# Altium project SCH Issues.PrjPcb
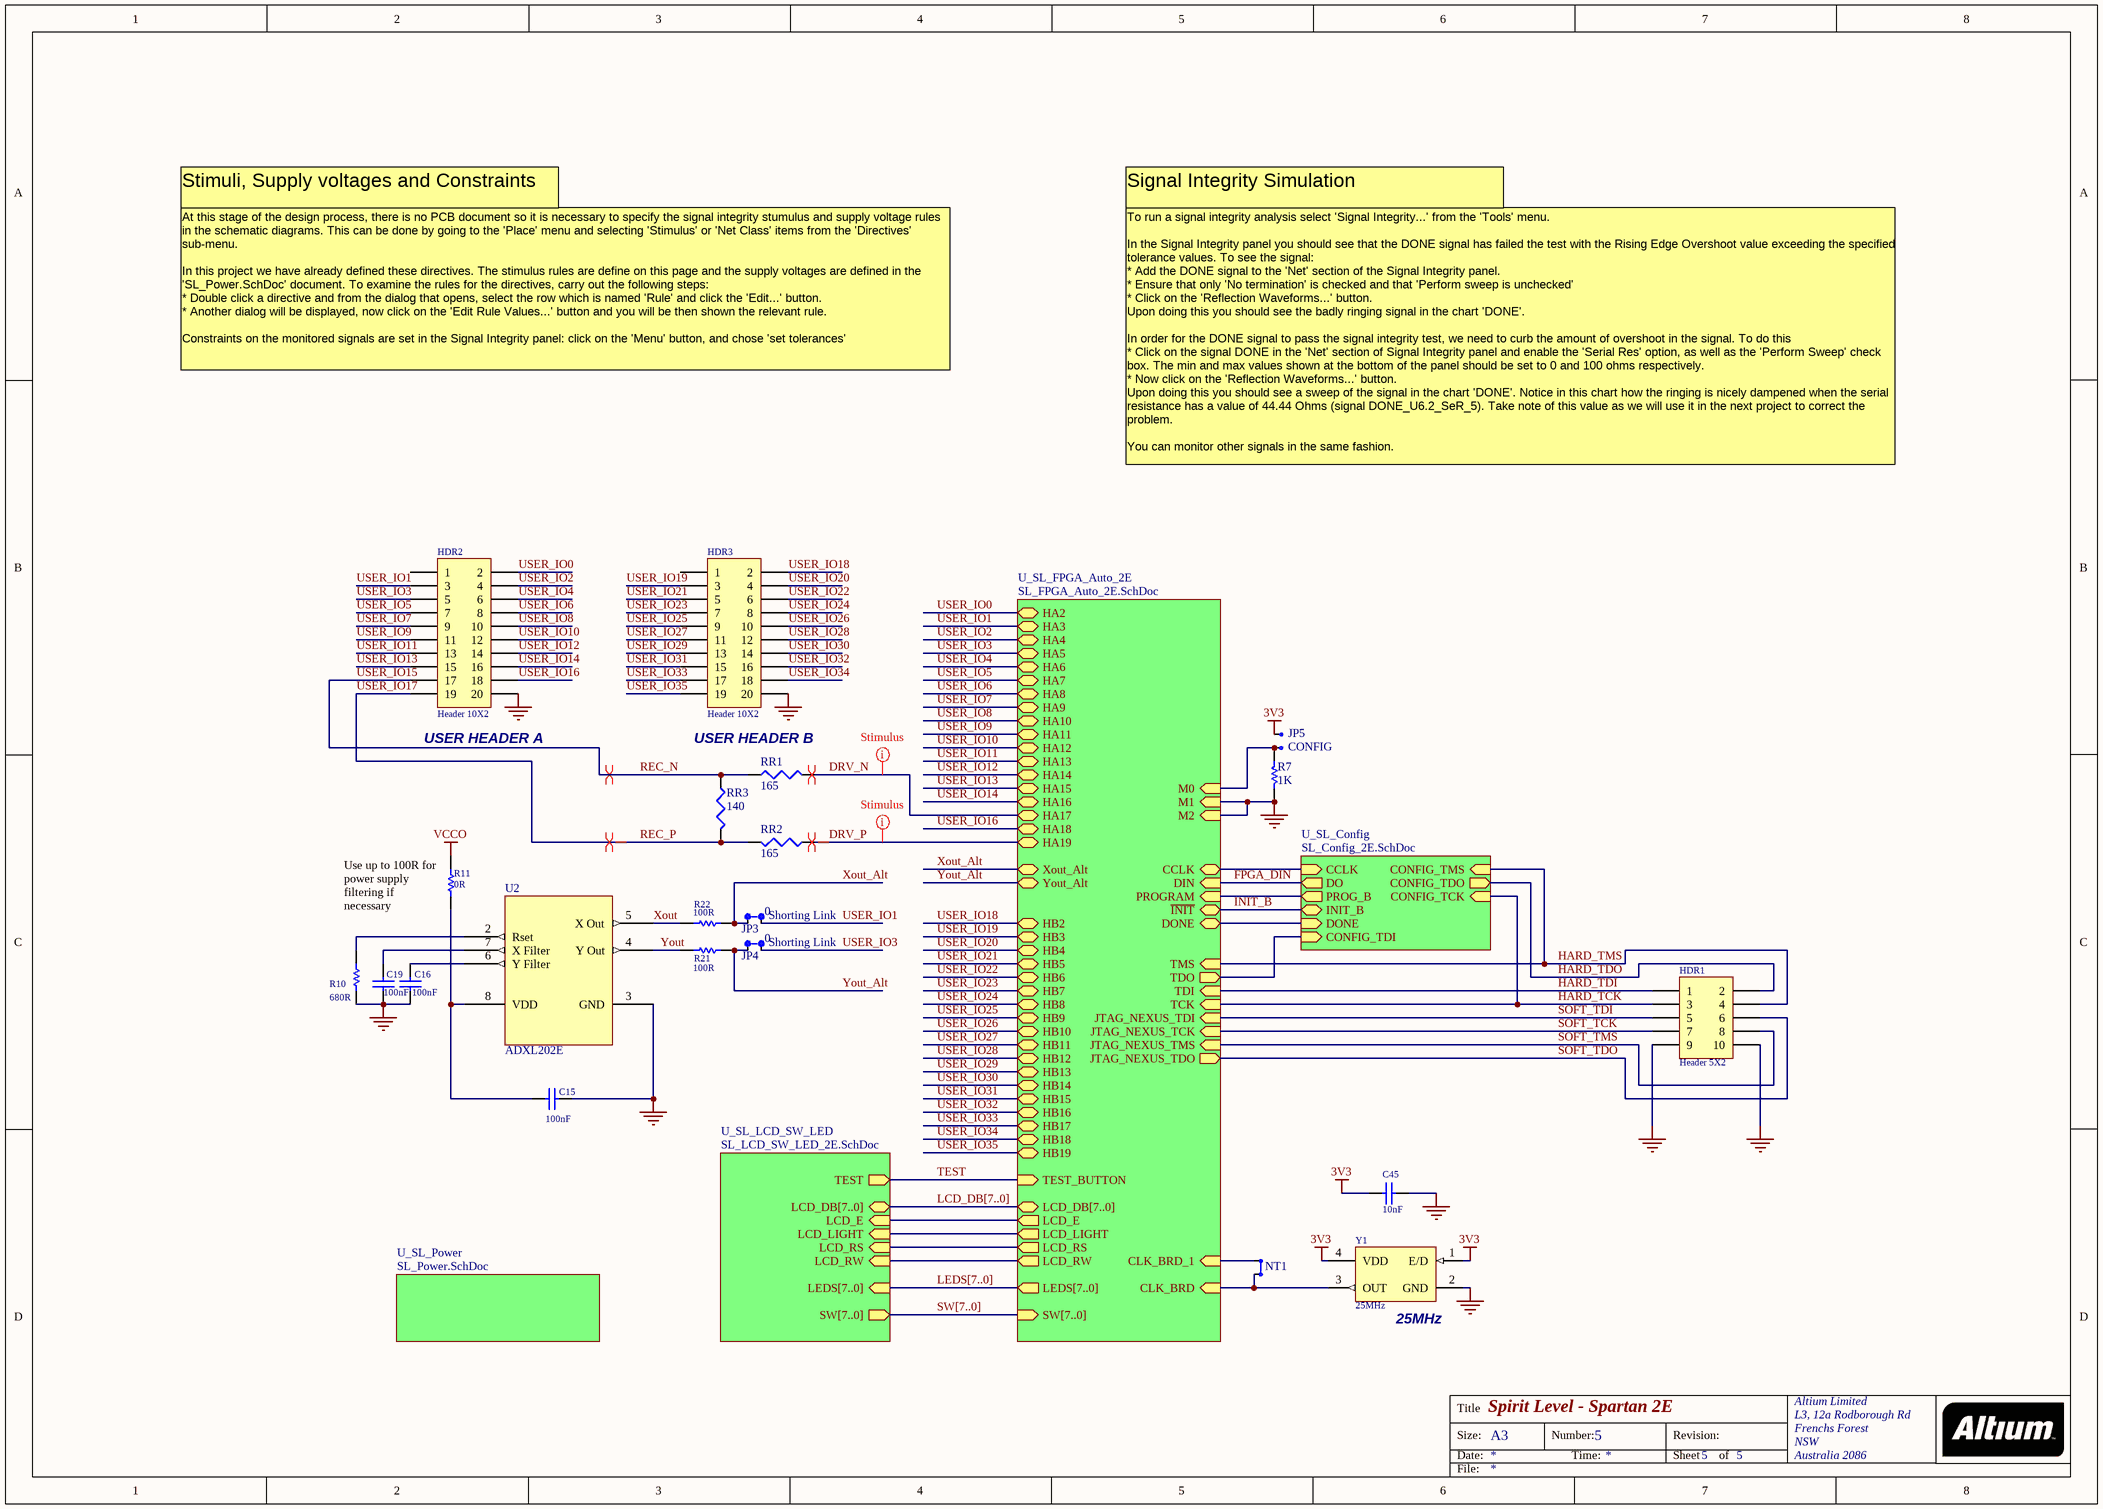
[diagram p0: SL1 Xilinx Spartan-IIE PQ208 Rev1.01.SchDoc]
5 sheets, 120 parts. Net scope: hierarchical (ports join the sheet entries above them; power ports are global).
Sheets:
  SL1 Xilinx Spartan-IIE PQ208 Rev1.01.SchDoc
    U_SL_Config = SL_Config_2E.SchDoc
    U_SL_LCD_SW_LED = SL_LCD_SW_LED_2E.SchDoc
    U_SL_FPGA_Auto_2E = SL_FPGA_Auto_2E.SchDoc
    U_SL_Power = SL_Power.SchDoc

## Sheet SL1 Xilinx Spartan-IIE PQ208 Rev1.01.SchDoc: Spirit Level - Spartan 2E
size A3; Organization: Altium Limited; Address1: L3, 12a Rodborough Rd; Address2: Frenchs Forest; Address3: NSW; Address4: Australia 2086; DocumentNumber: 5; SheetNumber: 5; SheetTotal: 5

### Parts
C15  100nF  [CC1608-0603]
C16  100nF  [CC1608-0603]
C19  100nF  [CC1608-0603]
C45  10nF  [CC1608-0603]
HDR1  Header 5X2  [HDR2X5_LP]
HDR2  Header 10X2  [HDR2X10]
HDR3  Header 10X2  [HDR2X10]
JP3  X axis  [HDR1X2]  (value not drawn)
JP4  Y axis  [HDR1X2]  (value not drawn)
JP5  CONFIG  [HDR1X2]
JS2  Shorting Link  value 0  (mechanical)
JS3  Shorting Link  value 0  (mechanical)
NT1  *  [NT]  (value not drawn)  (net tie, no BOM)
R7  1K  [CR2012-0805]
R10  680R  [CR2012-0805]
R11  0R  [CR2012-0805]
R21  100R  [CR2012-0805]
R22  100R  [CR2012-0805]
RR1  value 165  [J1-0603]  (hidden comment: Res3)
RR2  value 165  [J1-0603]  (hidden comment: Res3)
RR3  value 140  [J1-0603]  (hidden comment: Res3)
U2  ADXL202E  [E-8]
Y1  25MHz  [QSMO_4200]

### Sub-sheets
U_SL_Config = SL_Config_2E.SchDoc: PROG_B (out), CONFIG_TDO (out), DO (out), CCLK (in), CONFIG_TDI (in), CONFIG_TCK (in), CONFIG_TMS (in), INIT_B (bidir), DONE (in)
U_SL_FPGA_Auto_2E = SL_FPGA_Auto_2E.SchDoc: CLK_BRD (in), HA10 (bidir), HA11 (bidir), HA12 (bidir), HA13 (bidir), HA14 (bidir), HA15 (bidir), HA16 (bidir), HA17 (bidir), HA18 (bidir), HA19 (bidir), HA2 (bidir), HA3 (bidir), HA4 (bidir), HA5 (bidir), HA6 (bidir), HA7 (bidir), HA8 (bidir), HA9 (bidir), HB10 (bidir), HB11 (bidir), HB12 (bidir), HB13 (bidir), HB14 (bidir), HB15 (bidir), HB16 (bidir), HB17 (bidir), HB18 (bidir), HB19 (bidir), HB2 (bidir), HB3 (bidir), HB4 (bidir), HB5 (bidir), HB6 (bidir), HB7 (bidir), HB8 (bidir), HB9 (bidir), JTAG_NEXUS_TCK (in), JTAG_NEXUS_TDI (in), JTAG_NEXUS_TDO (out), JTAG_NEXUS_TMS (in), LCD_DB[7..0] (bidir), LCD_E (out), LCD_LIGHT (out), LCD_RS (out), LCD_RW (out), LEDS[7..0] (out), SW[7..0] (in), TEST_BUTTON (in), CCLK (bidir), DONE (bidir), M0 (in), M1 (in), M2 (in), PROGRAM (in), TCK (in), TDI (in), TDO (out), TMS (in), DIN (in), ~{INIT} (bidir), CLK_BRD_1 (in), Xout_Alt, Yout_Alt
U_SL_LCD_SW_LED = SL_LCD_SW_LED_2E.SchDoc: TEST (out), SW[7..0] (out), LCD_DB[7..0] (bidir), LCD_E (in), LCD_RS (in), LCD_RW (in), LCD_LIGHT (in), LEDS[7..0] (in)
U_SL_Power = SL_Power.SchDoc: no entries

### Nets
GND: C15.2 C16.2 C19.2 C45.2 HDR1.9 HDR1.10 HDR2.20 HDR3.20 R7.1 R10.1 U2.3(GND) Y1.2(GND) ; sheet U_SL_FPGA_Auto_2E/M1, sheet U_SL_FPGA_Auto_2E/M2
VCCO: C45.1 JP5.2 R11.1 Y1.1(E/D) Y1.4(VDD)  [also labelled 3V3]
CCLK: sheet U_SL_Config/CCLK, sheet U_SL_FPGA_Auto_2E/CCLK
CLK_BRD: NT1.2 Y1.3(OUT) ; sheet U_SL_FPGA_Auto_2E/CLK_BRD
CLK_BRD_1: NT1.1 ; sheet U_SL_FPGA_Auto_2E/CLK_BRD_1
DONE: sheet U_SL_Config/DONE, sheet U_SL_FPGA_Auto_2E/DONE
DRV_N: RR1.1 ; sheet U_SL_FPGA_Auto_2E/HA17
DRV_P: RR2.2 ; sheet U_SL_FPGA_Auto_2E/HA19
FPGA_DIN: sheet U_SL_Config/DO, sheet U_SL_FPGA_Auto_2E/DIN  [project net DIN]
HARD_TCK: HDR1.3 ; sheet U_SL_Config/CONFIG_TCK, sheet U_SL_FPGA_Auto_2E/TCK
HARD_TDI: HDR1.1 ; sheet U_SL_FPGA_Auto_2E/TDI
HARD_TDO: HDR1.2 ; sheet U_SL_Config/CONFIG_TDO
HARD_TMS: HDR1.4 ; sheet U_SL_Config/CONFIG_TMS, sheet U_SL_FPGA_Auto_2E/TMS
INIT_B: sheet U_SL_Config/INIT_B, sheet U_SL_FPGA_Auto_2E/~{INIT}  [project net ~{INIT}]
LCD_E: sheet U_SL_LCD_SW_LED/LCD_E, sheet U_SL_FPGA_Auto_2E/LCD_E
LCD_LIGHT: sheet U_SL_LCD_SW_LED/LCD_LIGHT, sheet U_SL_FPGA_Auto_2E/LCD_LIGHT
LCD_RS: sheet U_SL_LCD_SW_LED/LCD_RS, sheet U_SL_FPGA_Auto_2E/LCD_RS
LCD_RW: sheet U_SL_LCD_SW_LED/LCD_RW, sheet U_SL_FPGA_Auto_2E/LCD_RW
M0: JP5.1 R7.2 ; sheet U_SL_FPGA_Auto_2E/M0
PROG_B: sheet U_SL_Config/PROG_B, sheet U_SL_FPGA_Auto_2E/PROGRAM
REC_N: HDR2.17 RR1.2 RR3.2  [also labelled USER_IO15]
REC_P: HDR2.19 RR2.1 RR3.1  [also labelled USER_IO17]
SOFT_TCK: HDR1.7 ; sheet U_SL_FPGA_Auto_2E/JTAG_NEXUS_TCK  [project net JTAG_NEXUS_TCK]
SOFT_TDI: HDR1.5 ; sheet U_SL_FPGA_Auto_2E/JTAG_NEXUS_TDI  [project net JTAG_NEXUS_TDI]
SOFT_TDO: HDR1.6 ; sheet U_SL_FPGA_Auto_2E/JTAG_NEXUS_TDO  [project net JTAG_NEXUS_TDO]
SOFT_TMS: HDR1.8 ; sheet U_SL_FPGA_Auto_2E/JTAG_NEXUS_TMS  [project net JTAG_NEXUS_TMS]
TDI_C: sheet U_SL_Config/CONFIG_TDI, sheet U_SL_FPGA_Auto_2E/TDO
TEST: sheet U_SL_LCD_SW_LED/TEST, sheet U_SL_FPGA_Auto_2E/TEST_BUTTON
USER_IO0: HDR2.2 ; sheet U_SL_FPGA_Auto_2E/HA2  [project net HA2]
USER_IO1: HDR2.3 JP3.2 ; sheet U_SL_FPGA_Auto_2E/HA3  [project net HA3]
USER_IO2: HDR2.4 ; sheet U_SL_FPGA_Auto_2E/HA4  [project net HA4]
USER_IO3: HDR2.5 JP4.2 ; sheet U_SL_FPGA_Auto_2E/HA5  [project net HA5]
USER_IO4: HDR2.6 ; sheet U_SL_FPGA_Auto_2E/HA6  [project net HA6]
USER_IO5: HDR2.7 ; sheet U_SL_FPGA_Auto_2E/HA7  [project net HA7]
USER_IO6: HDR2.8 ; sheet U_SL_FPGA_Auto_2E/HA8  [project net HA8]
USER_IO7: HDR2.9 ; sheet U_SL_FPGA_Auto_2E/HA9  [project net HA9]
USER_IO8: HDR2.10 ; sheet U_SL_FPGA_Auto_2E/HA10  [project net HA10]
USER_IO9: HDR2.11 ; sheet U_SL_FPGA_Auto_2E/HA11  [project net HA11]
USER_IO10: HDR2.12 ; sheet U_SL_FPGA_Auto_2E/HA12  [project net HA12]
USER_IO11: HDR2.13 ; sheet U_SL_FPGA_Auto_2E/HA13  [project net HA13]
USER_IO12: HDR2.14 ; sheet U_SL_FPGA_Auto_2E/HA14  [project net HA14]
USER_IO13: HDR2.15 ; sheet U_SL_FPGA_Auto_2E/HA15  [project net HA15]
USER_IO14: HDR2.16 ; sheet U_SL_FPGA_Auto_2E/HA16  [project net HA16]
USER_IO16: HDR2.18 ; sheet U_SL_FPGA_Auto_2E/HA18  [project net HA18]
USER_IO18: HDR3.2 ; sheet U_SL_FPGA_Auto_2E/HB2  [project net HB2]
USER_IO19: HDR3.3 ; sheet U_SL_FPGA_Auto_2E/HB3  [project net HB3]
USER_IO20: HDR3.4 ; sheet U_SL_FPGA_Auto_2E/HB4  [project net HB4]
USER_IO21: HDR3.5 ; sheet U_SL_FPGA_Auto_2E/HB5  [project net HB5]
USER_IO22: HDR3.6 ; sheet U_SL_FPGA_Auto_2E/HB6  [project net HB6]
USER_IO23: HDR3.7 ; sheet U_SL_FPGA_Auto_2E/HB7  [project net HB7]
USER_IO24: HDR3.8 ; sheet U_SL_FPGA_Auto_2E/HB8  [project net HB8]
USER_IO25: HDR3.9 ; sheet U_SL_FPGA_Auto_2E/HB9  [project net HB9]
USER_IO26: HDR3.10 ; sheet U_SL_FPGA_Auto_2E/HB10  [project net HB10]
USER_IO27: HDR3.11 ; sheet U_SL_FPGA_Auto_2E/HB11  [project net HB11]
USER_IO28: HDR3.12 ; sheet U_SL_FPGA_Auto_2E/HB12  [project net HB12]
USER_IO29: HDR3.13 ; sheet U_SL_FPGA_Auto_2E/HB13  [project net HB13]
USER_IO30: HDR3.14 ; sheet U_SL_FPGA_Auto_2E/HB14  [project net HB14]
USER_IO31: HDR3.15 ; sheet U_SL_FPGA_Auto_2E/HB15  [project net HB15]
USER_IO32: HDR3.16 ; sheet U_SL_FPGA_Auto_2E/HB16  [project net HB16]
USER_IO33: HDR3.17 ; sheet U_SL_FPGA_Auto_2E/HB17  [project net HB17]
USER_IO34: HDR3.18 ; sheet U_SL_FPGA_Auto_2E/HB18  [project net HB18]
USER_IO35: HDR3.19 ; sheet U_SL_FPGA_Auto_2E/HB19  [project net HB19]
Xout: R22.2 U2.5(X_Out)
Xout_Alt: JP3.1 R22.1 ; sheet U_SL_FPGA_Auto_2E/Xout_Alt
Yout: R21.2 U2.4(Y_Out)
Yout_Alt: JP4.1 R21.1 ; sheet U_SL_FPGA_Auto_2E/Yout_Alt
NetC15_1: C15.1 R11.2 U2.8(VDD)
NetC16_1: C16.1 U2.6(Y_Filter)
NetC19_1: C19.1 U2.7(X_Filter)
NetR10_2: R10.2 U2.2(Rset)

Not connected (* = marked no-connect by the designer): HDR2 1; HDR3 1; U2 1(Self_Test)

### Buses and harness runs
bus LCD_DB[7..0] = sheet U_SL_FPGA_Auto_2E/LCD_DB[7..0] = sheet U_SL_LCD_SW_LED/LCD_DB[7..0]
bus LEDS[7..0] = sheet U_SL_FPGA_Auto_2E/LEDS[7..0] = sheet U_SL_LCD_SW_LED/LEDS[7..0]
bus SW[7..0] = sheet U_SL_FPGA_Auto_2E/SW[7..0] = sheet U_SL_LCD_SW_LED/SW[7..0]

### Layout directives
differential pair: DRV_N, DRV_P, REC_N, REC_P
rule Signal Stimulus [Kind - Single Pulse    Level - High    Start Time = 10.00n    Stop Time = 60.00n    Period Time = 100.0n]: DRV_N
rule Signal Stimulus [Kind - Single Pulse    Level - Low    Start Time = 10.00n    Stop Time = 60.00n    Period Time = 100.0n]: DRV_P

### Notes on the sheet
- Stimuli, Supply voltages and Constraints
- Signal Integrity Simulation
- At this stage of the design process, there is no PCB document so it is necessary to specify the signal integrity stumulus and supply voltage rules in the schematic diagrams. This can be done by going to the 'Place' menu and selecting 'Stimulus' or 'Net Class' items from the 'Directives' sub-menu.
  In this project we have already defined these directives. The stimulus rules are define on this page and the supply voltages are defined in the 'SL_Power.SchDoc' document. To examine the rules for the directives, carry out the following steps:
  * Double click a directive and from the dialog that opens, select the row which is named 'Rule' and click the 'Edit...' button.
  * Another dialog will be displayed, now click on the 'Edit Rule Values...' button and you will be then shown the relevant rule.
  Constraints on the monitored signals are set in the Signal Integrity panel: click on the 'Menu' button, and chose 'set tolerances'
- To run a signal integrity analysis select 'Signal Integrity...' from the 'Tools' menu.
  In the Signal Integrity panel you should see that the DONE signal has failed the test with the Rising Edge Overshoot value exceeding the specified tolerance values. To see the signal:
  * Add the DONE signal to the 'Net' section of the Signal Integrity panel.
  * Ensure that only 'No termination' is checked and that 'Perform sweep is unchecked'
  * Click on the 'Reflection Waveforms...' button.
  Upon doing this you should see the badly ringing signal in the chart 'DONE'.
  In order for the DONE signal to pass the signal integrity test, we need to curb the amount of overshoot in the signal. To do this
  * Click on the signal DONE in the 'Net' section of Signal Integrity panel and enable the 'Serial Res' option, as well as the 'Perform Sweep' check box. The min and max values shown at the bottom of the panel should be set to 0 and 100 ohms respectively.
  * Now click on the 'Reflection Waveforms...' button.
  Upon doing this you should see a sweep of the signal in the chart 'DONE'. Notice in this chart how the ringing is nicely dampened when the serial resistance has a value of 44.44 Ohms (signal DONE_U6.2_SeR_5). Take note of this value as we will use it in the next project to correct the problem.
  You can monitor other signals in the same fashion.
- (near HDR2) USER HEADER A
- USER HEADER B
- (near R11) Use up to 100R for power supply filtering if necessary
- (near Y1) 25MHz

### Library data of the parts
C15 C16 C19 = CAP: Capacitor; AEMS Code: 2101550
C45 = CAP: Capacitor; AEMS Code: 2100341
HDR1 = Header 5X2: Header, 5-Pin, Dual row
HDR2 HDR3 = Header 10X2: Header, 10-Pin, Dual row
JP3-JP5 NT1 = Jumper, 2-Pin
JS2 JS3 = Jumper Socket: Shorting Link, 2.54mm (0.1") Pitch
R7 = RES: Resistor; AEMS Code: 1200008JN
R10 = Res1: Resistor; AEMS Code: CHANGED VALUE
R11 = RES: Resistor; AEMS Code: 1200075
R21 R22 = Res1: Resistor; AEMS Code: 1200012JT
RR1-RR3 = Res3: Resistor
U2 = ADXL202E: Accelerometer with Digital Output
Y1 = QSMO_4200: Surface Mount Crystal Oscillator

## Sheet SL_Config_2E.SchDoc: FPGA Configuration
size A; Organization: Altium Limited; Address1: L3, 12a Rodborough Rd; Address2: Frenchs Forest; Address3: NSW; Address4: Australia 2086; DocumentNumber: 2; SheetNumber: 2; SheetTotal: 5
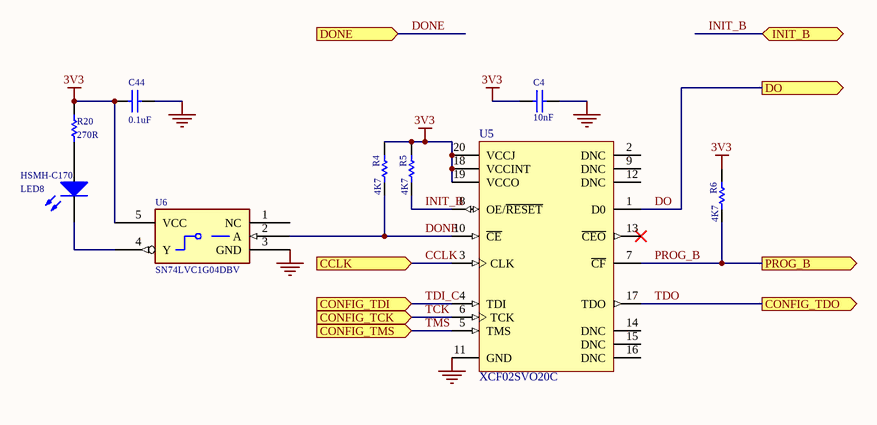
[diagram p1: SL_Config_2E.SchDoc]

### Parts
C4  10nF  [CC1608-0603]
C44  0.1uF  [CC2012-0805]
LED8  HSMH-C170  [SMD _LED]
R4  4K7  [CR2012-0805]
R5  4K7  [CR2012-0805]
R6  4K7  [CR2012-0805]
R20  270R  [CR2012-0805]
U5  XCF02SVO20C  [VO20]
U6  SN74LVC1G04DBV  [SO-G5/P.95]

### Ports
CCLK (in), CONFIG_TCK (in), CONFIG_TDI (in), CONFIG_TDO (out), CONFIG_TMS (in), DO (out), DONE (in), INIT_B (bidir), PROG_B (out)

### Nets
3V3: C4.1 C44.2 R4.1 R5.1 R6.1 R20.2 U5.18(VCCINT) U5.19(VCCO) U5.20(VCCJ) U6.5(VCC)  [project net VCCO]
GND: C4.2 C44.1 U5.11(GND) U6.3(GND)
CCLK: U5.3(CLK) ; port CCLK
DO: U5.1(D0) ; port DO  [project net DIN]
DONE: R4.2 U5.10(~{CE}) U6.2(A) ; port DONE
INIT_B: R5.2 U5.8(OE/~{RESET}) ; port INIT_B  [project net ~{INIT}]
PROG_B: R6.2 U5.7(~{CF}) ; port PROG_B
TCK: U5.6(TCK) ; port CONFIG_TCK  [project net HARD_TCK]
TDI_C: U5.4(TDI) ; port CONFIG_TDI
TDO: U5.17(TDO) ; port CONFIG_TDO  [project net HARD_TDO]
TMS: U5.5(TMS) ; port CONFIG_TMS  [project net HARD_TMS]
NetLED8_1: LED8.1(A) R20.1
NetLED8_2: LED8.2(K) U6.4(Y)

Not connected (* = marked no-connect by the designer): U5 2(DNC) 9(DNC) 12(DNC) 13(~{CEO})* 14(DNC) 15(DNC) 16(DNC); U6 1(NC)

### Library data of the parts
C4 = CAP: Capacitor; AEMS Code: 2100341
C44 = CAP: Capacitor
LED8 = HSMX-C670: Typical RED GaAs SMD LED Agilent make; AEMS Code: 2610081
R4-R6 = RES: Resistor; AEMS Code: 1200226
R20 = RES: Resistor; AEMS Code: 1200430
U5 = XCF02SVO20C: XCF00S Series, Platform Flash In-System Programmable Configuration 3.3V PROM, 20-Pin TSOP, 2-Megabit, Commercial Grade; PackageDocument: ver1.0, May-2003; AEMS Code: CHANGED VALUE
U6 = SN74AHC1G04DBVR: Manufacturer: TI

## Sheet SL_LCD_SW_LED_2E.SchDoc: LCD, Switches and LEDs
size B; Organization: Altium Limited; Address1: L3, 12a Rodborough Rd; Address2: Frenchs Forest; Address3: NSW; Address4: Australia 2086; DocumentNumber: 3; SheetNumber: 3; SheetTotal: 5
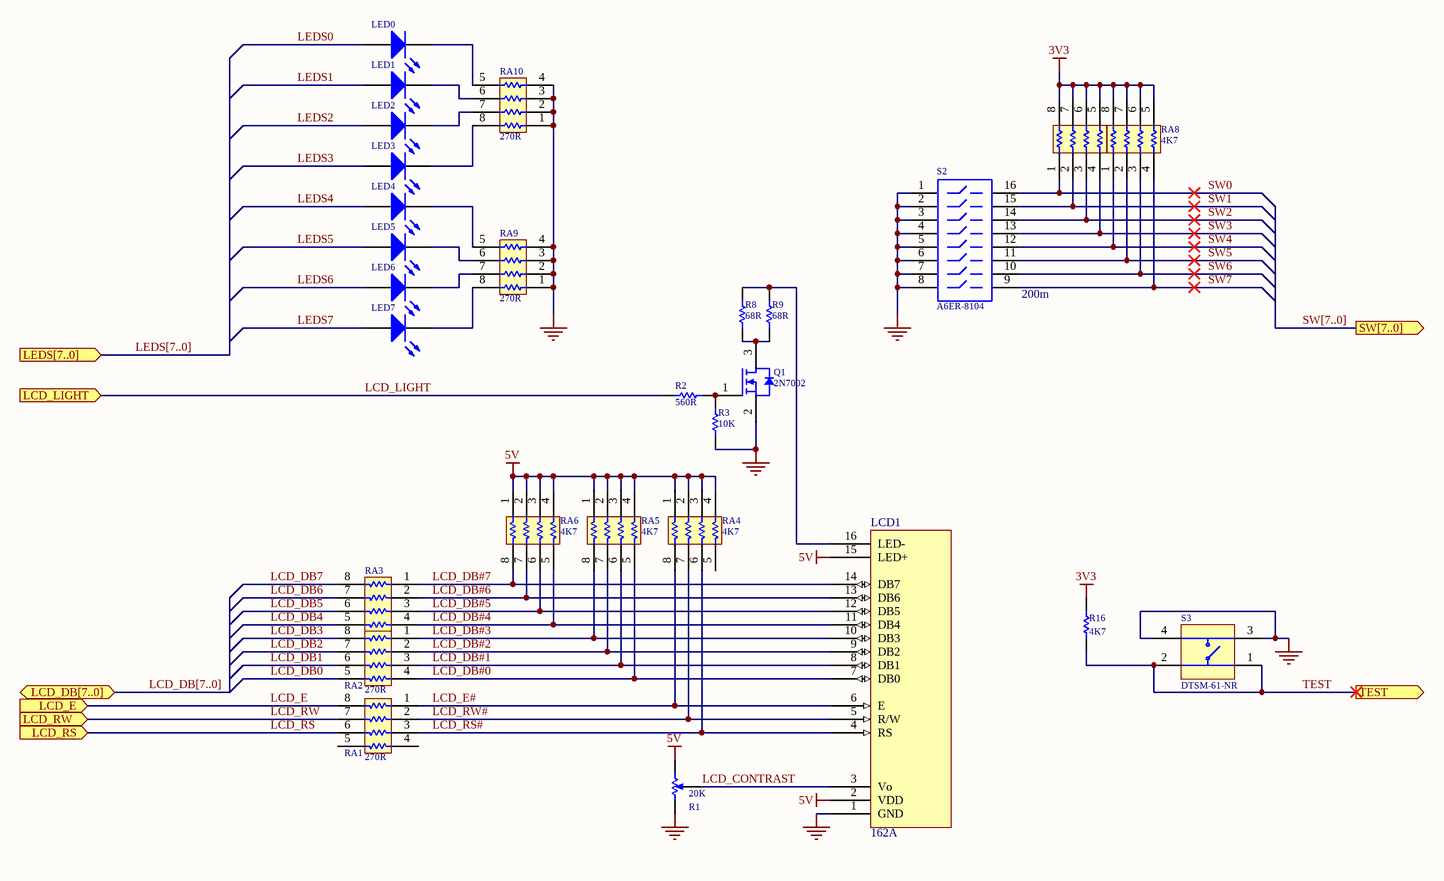
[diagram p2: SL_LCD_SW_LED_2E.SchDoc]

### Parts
LCD1  162A  [162A]
LED0  HSMH-C170  [SMD _LED]  (value not drawn)
LED1  HSMH-C170  [SMD _LED]  (value not drawn)
LED2  HSMH-C170  [SMD _LED]  (value not drawn)
LED3  HSMH-C170  [SMD _LED]  (value not drawn)
LED4  HSMH-C170  [SMD _LED]  (value not drawn)
LED5  HSMH-C170  [SMD _LED]  (value not drawn)
LED6  HSMH-C170  [SMD _LED]  (value not drawn)
LED7  HSMH-C170  [SMD _LED]  (value not drawn)
Q1  2N7002  [SO-G3]
R1  20K  [POT4MM-2]
R2  560R  [CC2012-0805]
R3  10K  [CC2012-0805]
R8  68R  [CC2012-0805]
R9  68R  [CC2012-0805]
R16  4K7  [CC2012-0805]
RA1  270R  [MNR34]
RA2  270R  [MNR34]
RA3  270R  [MNR34]
RA4  4K7  [MNR34T]
RA5  4K7  [MNR34T]
RA6  4K7  [MNR34T]
RA7  4K7  [MNR34T]
RA8  4K7  [MNR34T]
RA9  270R  [MNR34T]
RA10  270R  [MNR34T]
S2  A6ER-8104  value 200m  [DIP-16-KEY]
S3  DTSM-61-NR  [B3FS_SWITCH]

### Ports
LCD_DB[7..0] (bidir), LCD_E (in), LCD_LIGHT (in), LCD_RS (in), LCD_RW (in), LEDS[7..0] (in), SW[7..0] (out), TEST (out)

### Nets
3V3: R16.1 RA7.5 RA7.6 RA7.7 RA7.8 RA8.5 RA8.6 RA8.7 RA8.8  [project net VCCO]
5V: LCD1.2(VDD) LCD1.15(LED+) R1.CW(+) RA4.1 RA4.2 RA4.3 RA4.4 RA5.1 RA5.2 RA5.3 RA5.4 RA6.1 RA6.2 RA6.3 RA6.4
GND: LCD1.1(GND) Q1.2 R1.CCW(-) R3.1 RA9.1 RA9.2 RA9.3 RA9.4 RA10.1 RA10.2 RA10.3 RA10.4 S2.1 S2.2 S2.3 S2.4 S2.5 S2.6 S2.7 S2.8 S3.3 S3.4
LCD_CONTRAST: LCD1.3(Vo) R1.W
LCD_DB0: RA2.5
LCD_DB1: RA2.6
LCD_DB2: RA2.7
LCD_DB3: RA2.8
LCD_DB4: RA3.5
LCD_DB5: RA3.6
LCD_DB6: RA3.7
LCD_DB7: RA3.8
LCD_DB#0: LCD1.7(DB0) RA2.4 RA5.5
LCD_DB#1: LCD1.8(DB1) RA2.3 RA5.6
LCD_DB#2: LCD1.9(DB2) RA2.2 RA5.7
LCD_DB#3: LCD1.10(DB3) RA2.1 RA5.8
LCD_DB#4: LCD1.11(DB4) RA3.4 RA6.5
LCD_DB#5: LCD1.12(DB5) RA3.3 RA6.6
LCD_DB#6: LCD1.13(DB6) RA3.2 RA6.7
LCD_DB#7: LCD1.14(DB7) RA3.1 RA6.8
LCD_E: RA1.8 ; port LCD_E
LCD_E#: LCD1.6(E) RA1.1 RA4.8
LCD_LIGHT: R2.1 ; port LCD_LIGHT
LCD_RS: RA1.6 ; port LCD_RS
LCD_RS#: LCD1.4(RS) RA1.3 RA4.6
LCD_RW: RA1.7 ; port LCD_RW
LCD_RW#: LCD1.5(R/W) RA1.2 RA4.7
LEDS0: LED0.1(A)
LEDS1: LED1.1(A)
LEDS2: LED2.1(A)
LEDS3: LED3.1(A)
LEDS4: LED4.1(A)
LEDS5: LED5.1(A)
LEDS6: LED6.1(A)
LEDS7: LED7.1(A)
SW0: RA7.1 S2.16
SW1: RA7.2 S2.15
SW2: RA7.3 S2.14
SW3: RA7.4 S2.13
SW4: RA8.1 S2.12
SW5: RA8.2 S2.11
SW6: RA8.3 S2.10
SW7: RA8.4 S2.9
TEST: R16.2 S3.1 S3.2 ; port TEST
NetLCD1_16: LCD1.16(LED-) R8.1 R9.1
NetLED0_2: LED0.2(K) RA10.5
NetLED1_2: LED1.2(K) RA10.6
NetLED2_2: LED2.2(K) RA10.7
NetLED3_2: LED3.2(K) RA10.8
NetLED4_2: LED4.2(K) RA9.5
NetLED5_2: LED5.2(K) RA9.6
NetLED6_2: LED6.2(K) RA9.7
NetLED7_2: LED7.2(K) RA9.8
NetQ1_1: Q1.1 R2.2 R3.2
NetQ1_3: Q1.3 R8.2 R9.2

Not connected (* = marked no-connect by the designer): RA1 4 5; RA4 5

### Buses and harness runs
bus LCD_DB[7..0] = port LCD_DB[7..0]
bus LEDS[7..0] = port LEDS[7..0]
bus SW[7..0] = port SW[7..0]

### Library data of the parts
LCD1 = 162A: 16 char * 2 line LCD character display with b/light
LED0-LED7 = HSMX-C670: as LED8 on sheet SL_Config_2E
Q1 = 2N7002: N Channel Mosfet
R1 = RPot SM: Square Trimming Potentiometer; AEMS Code: 1400226
R2 = RES: Resistor; AEMS Code: 1200723
R3 = RES: Resistor; AEMS Code: 1200006JT
R8 R9 = RES: Resistor; AEMS Code: 1200821
R16 = RES: Resistor; AEMS Code: 1200226
RA1-RA3 RA9 RA10 = MNR34: 3216x4 Resistor Array; AEMS Code: 1310010
RA4-RA8 = MNR34: 3216x4 Resistor Array; AEMS Code: 1300330
S2 = A6ER-8104: DIP Switch Side actuator long liver Piano Key
S3 = B3FS: SPNA SMD Keyboard Switch

## Sheet SL_FPGA_Auto_2E.SchDoc
size C; Generated From FPGA Project: SpiritLevel.PRJFPG; UNUSED_SPECIAL: RouteSeparate; UNUSED_IO: Ignore; VREF: Ignore; UNUSED_INPUT: Ignore; DocumentNumber: 1; SheetNumber: 1; SheetTotal: 5
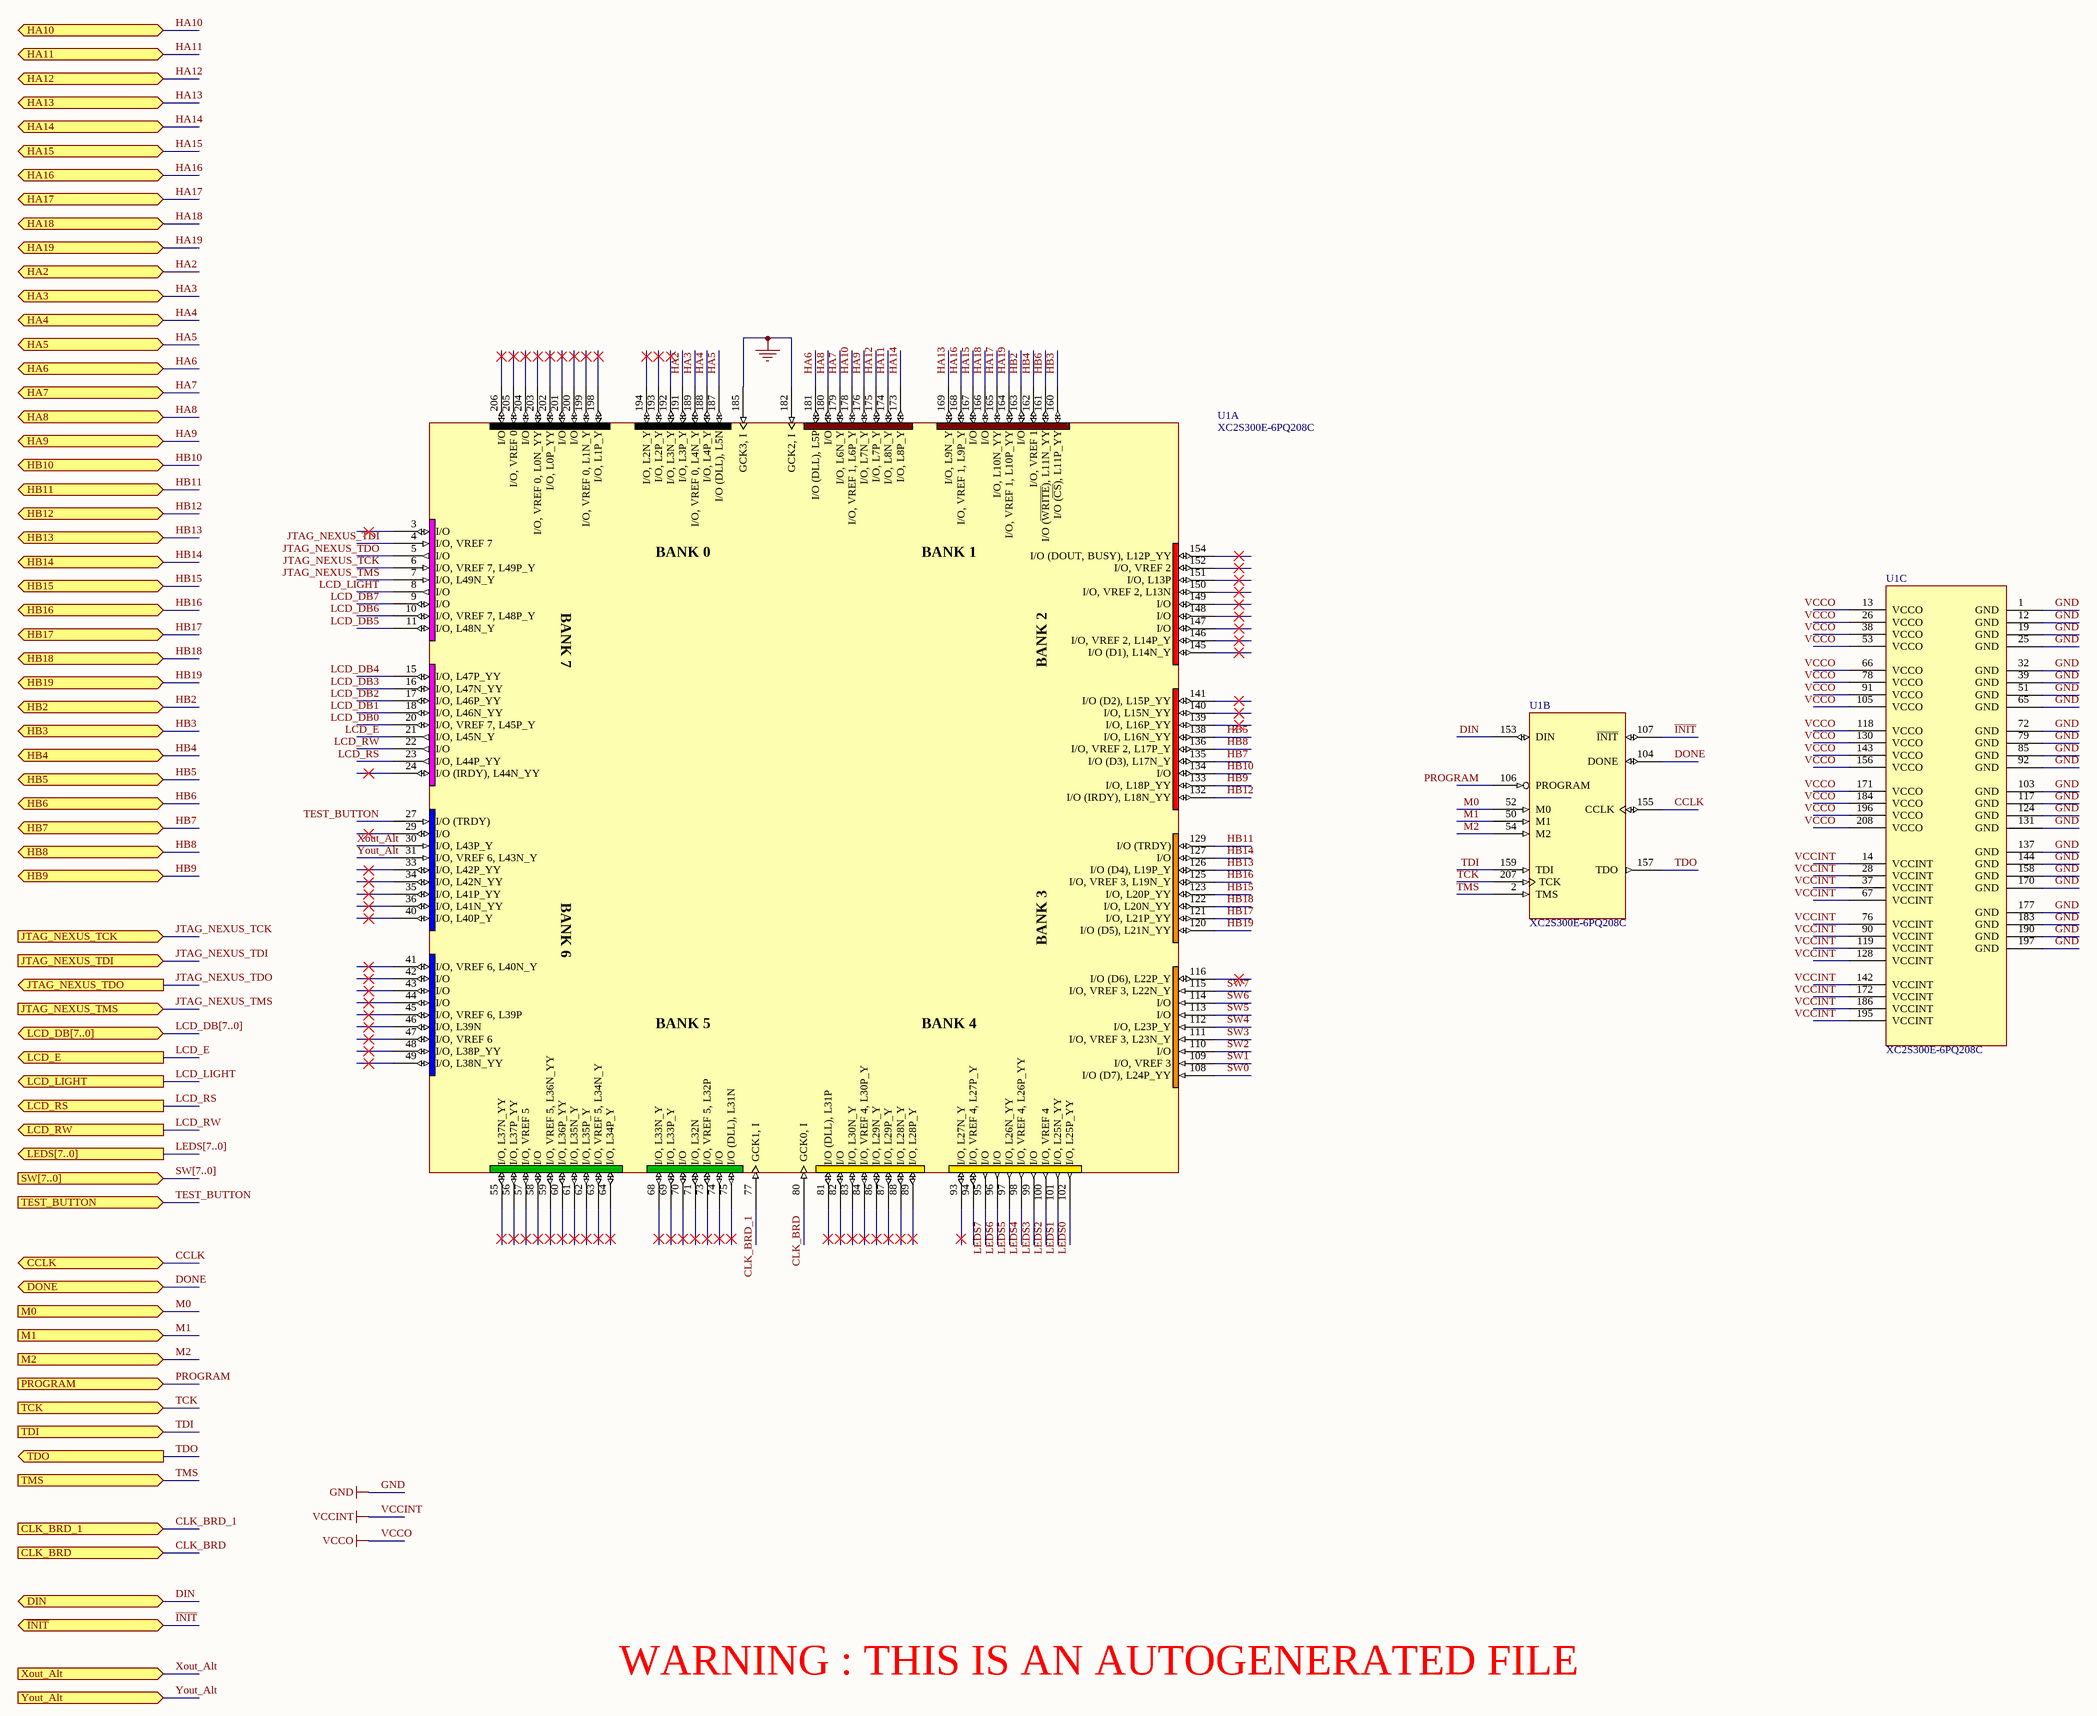
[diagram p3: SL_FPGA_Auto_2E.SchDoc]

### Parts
U1  XC2S300E-6PQ208C  [PQ208]  (parts A,B,C of 3)

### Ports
CCLK (bidir), CLK_BRD (in), CLK_BRD_1 (in), DIN (bidir), DONE (bidir), HA2 (bidir), HA3 (bidir), HA4 (bidir), HA5 (bidir), HA6 (bidir), HA7 (bidir), HA8 (bidir), HA9 (bidir), HA10 (bidir), HA11 (bidir), HA12 (bidir), HA13 (bidir), HA14 (bidir), HA15 (bidir), HA16 (bidir), HA17 (bidir), HA18 (bidir), HA19 (bidir), HB2 (bidir), HB3 (bidir), HB4 (bidir), HB5 (bidir), HB6 (bidir), HB7 (bidir), HB8 (bidir), HB9 (bidir), HB10 (bidir), HB11 (bidir), HB12 (bidir), HB13 (bidir), HB14 (bidir), HB15 (bidir), HB16 (bidir), HB17 (bidir), HB18 (bidir), HB19 (bidir), JTAG_NEXUS_TCK (in), JTAG_NEXUS_TDI (in), JTAG_NEXUS_TDO (out), JTAG_NEXUS_TMS (in), LCD_DB[7..0] (bidir), LCD_E (out), LCD_LIGHT (out), LCD_RS (out), LCD_RW (out), LEDS[7..0] (out), M0 (in), M1 (in), M2 (in), PROGRAM (in), SW[7..0] (in), TCK (in), TDI (in), TDO (out), TEST_BUTTON (in), TMS (in), Xout_Alt (in), Yout_Alt (in), ~{INIT} (bidir)

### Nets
GND: U1.1(GND) U1.12(GND) U1.19(GND) U1.25(GND) U1.32(GND) U1.39(GND) U1.50(M1) U1.51(GND) U1.54(M2) U1.65(GND) U1.72(GND) U1.79(GND) U1.85(GND) U1.92(GND) U1.103(GND) U1.117(GND) U1.124(GND) U1.131(GND) U1.137(GND) U1.144(GND) U1.158(GND) U1.170(GND) U1.177(GND) U1.182(GCK2,_I) U1.183(GND) U1.185(GCK3,_I) U1.190(GND) U1.197(GND) ; port M1, port M2  [also labelled M1, M2]
VCCINT: U1.14(VCCINT) U1.28(VCCINT) U1.37(VCCINT) U1.67(VCCINT) U1.76(VCCINT) U1.90(VCCINT) U1.119(VCCINT) U1.128(VCCINT) U1.142(VCCINT) U1.172(VCCINT) U1.186(VCCINT) U1.195(VCCINT)
VCCO: U1.13(VCCO) U1.26(VCCO) U1.38(VCCO) U1.53(VCCO) U1.66(VCCO) U1.78(VCCO) U1.91(VCCO) U1.105(VCCO) U1.118(VCCO) U1.130(VCCO) U1.143(VCCO) U1.156(VCCO) U1.171(VCCO) U1.184(VCCO) U1.196(VCCO) U1.208(VCCO)
CCLK: U1.155(CCLK) ; port CCLK
CLK_BRD: U1.80(GCK0,_I) ; port CLK_BRD
CLK_BRD_1: U1.77(GCK1,_I) ; port CLK_BRD_1
DIN: U1.153(DIN) ; port DIN
DONE: U1.104(DONE) ; port DONE
HA2: U1.191(I/O,_L3P_Y) ; port HA2
HA3: U1.189(I/O,_VREF_0,_L4N_Y) ; port HA3
HA4: U1.188(I/O,_L4P_Y) ; port HA4
HA5: U1.187(I/O_(DLL),_L5N) ; port HA5
HA6: U1.181(I/O_(DLL),_L5P) ; port HA6
HA7: U1.179(I/O,_L6N_Y) ; port HA7
HA8: U1.180(I/O) ; port HA8
HA9: U1.176(I/O,_L7N_Y) ; port HA9
HA10: U1.178(I/O,_VREF_1,_L6P_Y) ; port HA10
HA11: U1.174(I/O,_L8N_Y) ; port HA11
HA12: U1.175(I/O,_L7P_Y) ; port HA12
HA13: U1.169(I/O,_L9N_Y) ; port HA13
HA14: U1.173(I/O,_L8P_Y) ; port HA14
HA15: U1.167(I/O) ; port HA15
HA16: U1.168(I/O,_VREF_1,_L9P_Y) ; port HA16
HA17: U1.165(I/O,_L10N_YY) ; port HA17  [project net DRV_N]
HA18: U1.166(I/O) ; port HA18
HA19: U1.164(I/O,_VREF_1,_L10P_YY) ; port HA19  [project net DRV_P]
HB2: U1.163(I/O) ; port HB2
HB3: U1.160(I/O_(~{CS}),_L11P_YY) ; port HB3
HB4: U1.162(I/O,_VREF_1) ; port HB4
HB5: U1.138(I/O,_L16N_YY) ; port HB5
HB6: U1.161(I/O_(~{WRITE}),_L11N_YY) ; port HB6
HB7: U1.135(I/O_(D3),_L17N_Y) ; port HB7
HB8: U1.136(I/O,_VREF_2,_L17P_Y) ; port HB8
HB9: U1.133(I/O,_L18P_YY) ; port HB9
HB10: U1.134(I/O) ; port HB10
HB11: U1.129(I/O_(TRDY)) ; port HB11
HB12: U1.132(I/O_(IRDY),_L18N_YY) ; port HB12
HB13: U1.126(I/O_(D4),_L19P_Y) ; port HB13
HB14: U1.127(I/O) ; port HB14
HB15: U1.123(I/O,_L20P_YY) ; port HB15
HB16: U1.125(I/O,_VREF_3,_L19N_Y) ; port HB16
HB17: U1.121(I/O,_L21P_YY) ; port HB17
HB18: U1.122(I/O,_L20N_YY) ; port HB18
HB19: U1.120(I/O_(D5),_L21N_YY) ; port HB19
~{INIT}: U1.107(~{INIT}) ; port ~{INIT}
JTAG_NEXUS_TCK: U1.6(I/O,_VREF_7,_L49P_Y) ; port JTAG_NEXUS_TCK
JTAG_NEXUS_TDI: U1.4(I/O,_VREF_7) ; port JTAG_NEXUS_TDI
JTAG_NEXUS_TDO: U1.5(I/O) ; port JTAG_NEXUS_TDO
JTAG_NEXUS_TMS: U1.7(I/O,_L49N_Y) ; port JTAG_NEXUS_TMS
LCD_DB0: U1.20(I/O,_VREF_7,_L45P_Y)
LCD_DB1: U1.18(I/O,_L46N_YY)
LCD_DB2: U1.17(I/O,_L46P_YY)
LCD_DB3: U1.16(I/O,_L47N_YY)
LCD_DB4: U1.15(I/O,_L47P_YY)
LCD_DB5: U1.11(I/O,_L48N_Y)
LCD_DB6: U1.10(I/O,_VREF_7,_L48P_Y)
LCD_DB7: U1.9(I/O)
LCD_E: U1.21(I/O,_L45N_Y) ; port LCD_E
LCD_LIGHT: U1.8(I/O) ; port LCD_LIGHT
LCD_RS: U1.23(I/O,_L44P_YY) ; port LCD_RS
LCD_RW: U1.22(I/O) ; port LCD_RW
LEDS0: U1.102(I/O,_L25P_YY)
LEDS1: U1.101(I/O,_L25N_YY)
LEDS2: U1.100(I/O,_VREF_4)
LEDS3: U1.99(I/O)
LEDS4: U1.98(I/O,_VREF_4,_L26P_YY)
LEDS5: U1.97(I/O,_L26N_YY)
LEDS6: U1.96(I/O)
LEDS7: U1.95(I/O)
M0: U1.52(M0) ; port M0
PROGRAM: U1.106(PROGRAM) ; port PROGRAM  [project net PROG_B]
SW0: U1.108(I/O_(D7),_L24P_YY)
SW1: U1.109(I/O,_VREF_3)
SW2: U1.110(I/O)
SW3: U1.111(I/O,_VREF_3,_L23N_Y)
SW4: U1.112(I/O,_L23P_Y)
SW5: U1.113(I/O)
SW6: U1.114(I/O)
SW7: U1.115(I/O,_VREF_3,_L22N_Y)
TCK: U1.207(TCK) ; port TCK  [project net HARD_TCK]
TDI: U1.159(TDI) ; port TDI  [project net HARD_TDI]
TDO: U1.157(TDO) ; port TDO  [project net TDI_C]
TEST_BUTTON: U1.27(I/O_(TRDY)) ; port TEST_BUTTON  [project net TEST]
TMS: U1.2(TMS) ; port TMS  [project net HARD_TMS]
Xout_Alt: U1.30(I/O,_L43P_Y) ; port Xout_Alt
Yout_Alt: U1.31(I/O,_VREF_6,_L43N_Y) ; port Yout_Alt

Not connected (* = marked no-connect by the designer): U1 3(I/O)* 24(I/O_(IRDY),_L44N_YY)* 29(I/O)* 33(I/O,_L42P_YY)* 34(I/O,_L42N_YY)* 35(I/O,_L41P_YY)* 36(I/O,_L41N_YY)* 40(I/O,_L40P_Y)* 41(I/O,_VREF_6,_L40N_Y)* 42(I/O)* 43(I/O)* 44(I/O)* 45(I/O,_VREF_6,_L39P)* 46(I/O,_L39N)* 47(I/O,_VREF_6)* 48(I/O,_L38P_YY)* 49(I/O,_L38N_YY)* 55(I/O,_L37N_YY)* 56(I/O,_L37P_YY)* 57(I/O,_VREF_5)* 58(I/O)* 59(I/O,_VREF_5,_L36N_YY)* 60(I/O,_L36P_YY)* 61(I/O,_L35N_Y)* 62(I/O,_L35P_Y)* 63(I/O,_VREF_5,_L34N_Y)* 64(I/O,_L34P_Y)* 68(I/O,_L33N_Y)* 69(I/O,_L33P_Y)* 70(I/O)* 71(I/O,_L32N)* 73(I/O,_VREF_5,_L32P)* 74(I/O)* 75(I/O_(DLL),_L31N)* 81(I/O_(DLL),_L31P)* 82(I/O)* 83(I/O,_L30N_Y)* 84(I/O,_VREF_4,_L30P_Y)* 86(I/O,_L29N_Y)* 87(I/O,_L29P_Y)* 88(I/O,_L28N_Y)* 89(I/O,_L28P_Y)* 93(I/O,_L27N_Y)* 94(I/O,_VREF_4,_L27P_Y) 116(I/O_(D6),_L22P_Y)* 139(I/O,_L16P_YY)* 140(I/O,_L15N_YY)* 141(I/O_(D2),_L15P_YY)* 145(I/O_(D1),_L14N_Y)* 146(I/O,_VREF_2,_L14P_Y)* 147(I/O)* 148(I/O)* 149(I/O)* 150(I/O,_VREF_2,_L13N)* 151(I/O,_L13P)* 152(I/O,_VREF_2)* 154(I/O_(DOUT,_BUSY),_L12P_YY)* 192(I/O,_L3N_Y)* 193(I/O,_L2P_Y)* 194(I/O,_L2N_Y)* 198(I/O,_L1P_Y)* 199(I/O,_VREF_0,_L1N_Y)* 200(I/O)* 201(I/O)* 202(I/O,_L0P_YY)* 203(I/O,_VREF_0,_L0N_YY)* 204(I/O)* 205(I/O,_VREF_0)* 206(I/O)*

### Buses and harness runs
bus LCD_DB[7..0] = port LCD_DB[7..0]
bus LEDS[7..0] = port LEDS[7..0]
bus SW[7..0] = port SW[7..0]

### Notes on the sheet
- WARNING : THIS IS AN AUTOGENERATED FILE

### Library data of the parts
U1 = XC2S300E-6PQ208C: Spartan-IIE 1.8V FPGA, 208-Pin PQFP, Standard Performance, Commercial Grade; Package Information: Latest Revision: ver1.1, Oct-2002; Code - JEDEC: MS-029-FA-1

## Sheet SL_Power.SchDoc: Power Supply
size B; Organization: Altium Limited; Address1: L3, 12a Rodborough Rd; Address2: Frenchs Forest; Address3: NSW; Address4: Australia 2086; DocumentNumber: 4; SheetNumber: 4; SheetTotal: 5
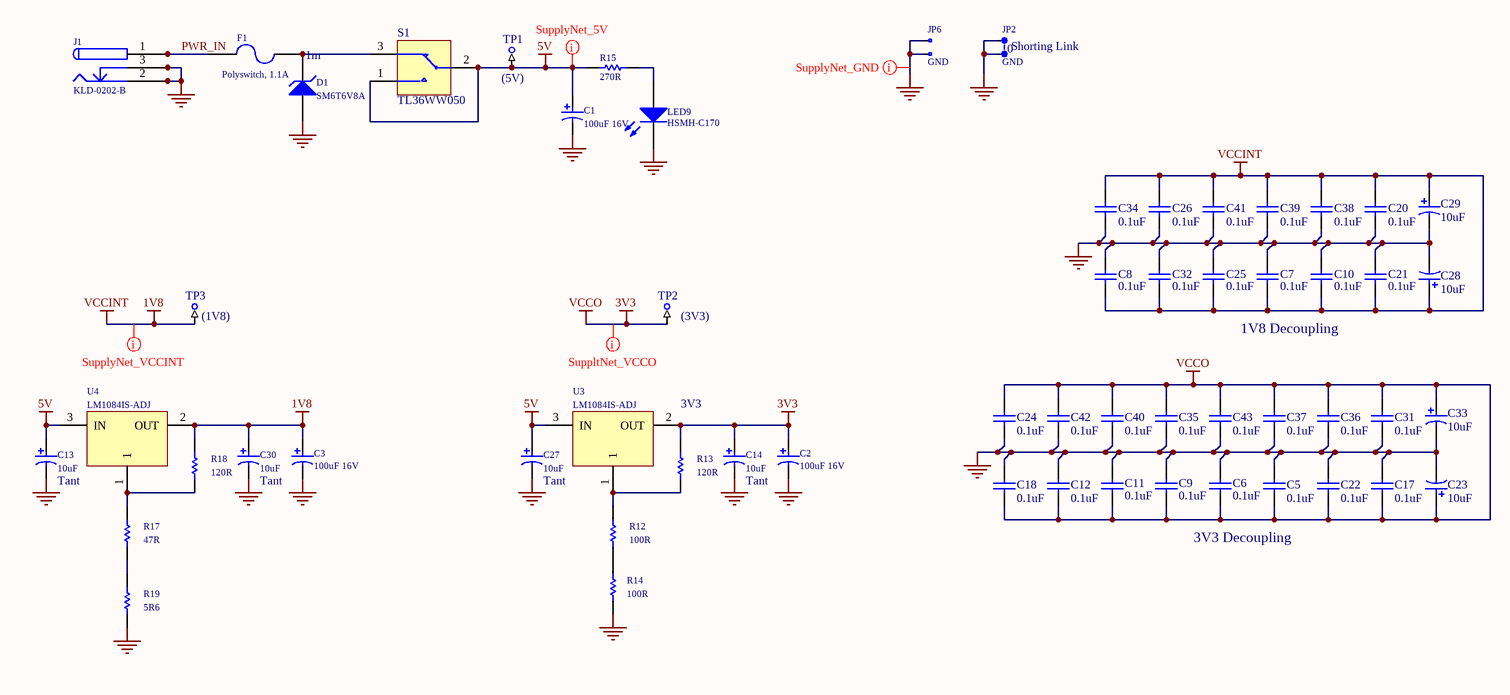
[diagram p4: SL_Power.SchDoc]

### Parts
C1  100uF 16V  [CAPPR2-5x6.8]
C2  100uF 16V  [CAPPR2-5x6.8]
C3  100uF 16V  [CAPPR2-5x6.8]
C5  0.1uF  [CC2012-0805]
C6  0.1uF  [CC2012-0805]
C7  0.1uF  [CC2012-0805]
C8  0.1uF  [CC2012-0805]
C9  0.1uF  [CC2012-0805]
C10  0.1uF  [CC2012-0805]
C11  0.1uF  [CC2012-0805]
C12  0.1uF  [CC2012-0805]
C13  10uF  Capacitor Type: Tant  [MCCT-B]
C14  10uF  Capacitor Type: Tant  [MCCT-B]
C17  0.1uF  [CC2012-0805]
C18  0.1uF  [CC2012-0805]
C20  0.1uF  [CC2012-0805]
C21  0.1uF  [CC2012-0805]
C22  0.1uF  [CC2012-0805]
C23  10uF  [MCCT-B]
C24  0.1uF  [CC2012-0805]
C25  0.1uF  [CC2012-0805]
C26  0.1uF  [CC2012-0805]
C27  10uF  Capacitor Type: Tant  [MCCT-B]
C28  10uF  [MCCT-B]
C29  10uF  [MCCT-B]
C30  10uF  Capacitor Type: Tant  [MCCT-B]
C31  0.1uF  [CC2012-0805]
C32  0.1uF  [CC2012-0805]
C33  10uF  [MCCT-B]
C34  0.1uF  [CC2012-0805]
C35  0.1uF  [CC2012-0805]
C36  0.1uF  [CC2012-0805]
C37  0.1uF  [CC2012-0805]
C38  0.1uF  [CC2012-0805]
C39  0.1uF  [CC2012-0805]
C40  0.1uF  [CC2012-0805]
C41  0.1uF  [CC2012-0805]
C42  0.1uF  [CC2012-0805]
C43  0.1uF  [CC2012-0805]
D1  SM6T6V8A  [DO214]
F1  Polyswitch, 1.1A  value 1m  [RUE160_0.2]
J1  KLD-0202-B  [KLD-0202]
JP2  GND  [HDR1X2]
JP6  GND  [HDR1X2]
JS1  Shorting Link  value 0  (mechanical)
LED9  HSMH-C170  [SMD _LED]
R12  100R  [CC2012-0805]
R13  120R  [CC2012-0805]
R14  100R  [CC2012-0805]
R15  270R  [CR2012-0805]
R17  47R  [CC2012-0805]
R18  120R  [CC2012-0805]
R19  5R6  [CC2012-0805]
S1  TL36WW050  [PCB_SWITCH]
TP1  (5V)  [TP]  (no BOM)
TP2  (3V3)  [TP]  (no BOM)
TP3  (1V8)  [TP]  (no BOM)
U3  LM1084IS-ADJ  [TO-263]
U4  LM1084IS-ADJ  [TO-263]

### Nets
5V: C1.1 C13.1 C27.1 R15.2 S1.1 S1.2 TP1.1 U3.3(IN) U4.3(IN)
GND: C1.2 C2.2 C3.2 C5.1 C6.2 C7.2 C8.2 C9.2 C10.2 C11.2 C12.2 C13.2 C14.2 C17.1 C18.1 C20.2 C21.2 C22.1 C23.2 C24.1 C25.2 C26.2 C27.2 C28.2 C29.2 C30.2 C31.2 C32.2 C33.2 C34.1 C35.2 C36.1 C37.2 C38.2 C39.2 C40.2 C41.2 C42.2 C43.2 D1.1(A) J1.2 J1.2A J1.2B J1.3 J1.3A J1.3B JP2.1 JP2.2 JP6.1 JP6.2 LED9.2(K) R14.1 R19.2
VCCINT: C3.1 C7.1 C8.1 C10.1 C20.1 C21.1 C25.1 C26.1 C28.1 C29.1 C30.1 C32.1 C34.2 C38.1 C39.1 C41.1 R18.1 TP3.1 U4.2(OUT)  [also labelled 1V8]
VCCO: C2.1 C5.2 C6.1 C9.1 C11.1 C12.1 C14.1 C17.2 C18.2 C22.2 C23.1 C24.2 C31.1 C33.1 C35.1 C36.2 C37.1 C40.1 C42.1 C43.1 R13.1 TP2.1 U3.2(OUT)  [also labelled 3V3]
PWR_IN: F1.1 J1.1 J1.1A J1.1B
NetD1_2: D1.2(K) F1.2 S1.3
NetLED9_1: LED9.1(A) R15.1
NetR12_1: R12.1 R13.2 U3.1
NetR12_2: R12.2 R14.2
NetR17_1: R17.1 R18.2 U4.1
NetR17_2: R17.2 R19.1

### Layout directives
rule Supply Nets [Voltage = 1.800]: VCCINT
rule Supply Nets [Voltage = 3.300]: VCCO
rule Supply Nets [Voltage = 0.000]: GND
rule Supply Nets [Voltage = 5.000]: 5V

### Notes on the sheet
- 1V8 Decoupling
- 3V3
- 3V3 Decoupling

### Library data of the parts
C1-C3 = CAP_POLAR: Polar Capacitor
C5-C12 C17 C18 C20-C22 C24-C26 C31 C32 C34-C43 = CAP: Capacitor
C13 C14 C23 C27-C30 C33 = CAP_POLAR: Polar Capacitor; AEMS Code: 2100110
D1 = BZG03C13: Zener Diode, 6.2V, 5W; Manufacturer: Microsemi
F1 = Fuse 2: Polyswitch 1.1A, Raychem RUE110
J1 = KLD-0202-B: Low Voltage Power Supply Connector; Manufacturer: Kycon; AEMS Code: 3510211
JP2 JP6 = Jumper, 2-Pin
JS1 = Jumper Socket: Shorting Link, 2.54mm (0.1") Pitch
LED9 = HSMX-C670: as LED8 on sheet SL_Config_2E
R12 R14 = RES: Resistor; AEMS Code: 1200012JT
R13 R18 = RES: Resistor; AEMS Code: 1200781
R15 = RES: Resistor; AEMS Code: 1200430
R17 = RES: Resistor; AEMS Code: CHANGED VALUE
R19 = RES: Resistor; AEMS Code: 1200069
S1 = PCB_MOUNT_SWITCH: SPDT Subminiature Toggle Switch
TP1-TP3 = TestPin
U3 U4 = LM1084IS-ADJ: 5A Low Dropout Possitive Regulators

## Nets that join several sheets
5V: SL_LCD_SW_LED_2E (15 pins), SL_Power (9 pins)
GND: SL1 Xilinx Spartan-IIE PQ208 Rev1.01 (12 pins), SL_Config_2E (C4.2 C44.1 U5.11 U6.3), SL_LCD_SW_LED_2E (22 pins), SL_FPGA_Auto_2E (28 pins), SL_Power (53 pins)
VCCINT: SL_FPGA_Auto_2E (12 pins), SL_Power (19 pins)
VCCO: SL1 Xilinx Spartan-IIE PQ208 Rev1.01 (5 pins), SL_Config_2E (10 pins), SL_LCD_SW_LED_2E (9 pins), SL_FPGA_Auto_2E (16 pins), SL_Power (23 pins)
CCLK: SL_Config_2E (U5.3), SL_FPGA_Auto_2E (U1.155)
CLK_BRD: SL1 Xilinx Spartan-IIE PQ208 Rev1.01 (NT1.2 Y1.3), SL_FPGA_Auto_2E (U1.80)
CLK_BRD_1: SL1 Xilinx Spartan-IIE PQ208 Rev1.01 (NT1.1), SL_FPGA_Auto_2E (U1.77)
DIN: SL_Config_2E (U5.1), SL_FPGA_Auto_2E (U1.153)
DONE: SL_Config_2E (R4.2 U5.10 U6.2), SL_FPGA_Auto_2E (U1.104)
DRV_N: SL1 Xilinx Spartan-IIE PQ208 Rev1.01 (RR1.1), SL_FPGA_Auto_2E (U1.165)
DRV_P: SL1 Xilinx Spartan-IIE PQ208 Rev1.01 (RR2.2), SL_FPGA_Auto_2E (U1.164)
HA2: SL1 Xilinx Spartan-IIE PQ208 Rev1.01 (HDR2.2), SL_FPGA_Auto_2E (U1.191)
HA3: SL1 Xilinx Spartan-IIE PQ208 Rev1.01 (HDR2.3 JP3.2), SL_FPGA_Auto_2E (U1.189)
HA4: SL1 Xilinx Spartan-IIE PQ208 Rev1.01 (HDR2.4), SL_FPGA_Auto_2E (U1.188)
HA5: SL1 Xilinx Spartan-IIE PQ208 Rev1.01 (HDR2.5 JP4.2), SL_FPGA_Auto_2E (U1.187)
HA6: SL1 Xilinx Spartan-IIE PQ208 Rev1.01 (HDR2.6), SL_FPGA_Auto_2E (U1.181)
HA7: SL1 Xilinx Spartan-IIE PQ208 Rev1.01 (HDR2.7), SL_FPGA_Auto_2E (U1.179)
HA8: SL1 Xilinx Spartan-IIE PQ208 Rev1.01 (HDR2.8), SL_FPGA_Auto_2E (U1.180)
HA9: SL1 Xilinx Spartan-IIE PQ208 Rev1.01 (HDR2.9), SL_FPGA_Auto_2E (U1.176)
HA10: SL1 Xilinx Spartan-IIE PQ208 Rev1.01 (HDR2.10), SL_FPGA_Auto_2E (U1.178)
HA11: SL1 Xilinx Spartan-IIE PQ208 Rev1.01 (HDR2.11), SL_FPGA_Auto_2E (U1.174)
HA12: SL1 Xilinx Spartan-IIE PQ208 Rev1.01 (HDR2.12), SL_FPGA_Auto_2E (U1.175)
HA13: SL1 Xilinx Spartan-IIE PQ208 Rev1.01 (HDR2.13), SL_FPGA_Auto_2E (U1.169)
HA14: SL1 Xilinx Spartan-IIE PQ208 Rev1.01 (HDR2.14), SL_FPGA_Auto_2E (U1.173)
HA15: SL1 Xilinx Spartan-IIE PQ208 Rev1.01 (HDR2.15), SL_FPGA_Auto_2E (U1.167)
HA16: SL1 Xilinx Spartan-IIE PQ208 Rev1.01 (HDR2.16), SL_FPGA_Auto_2E (U1.168)
HA18: SL1 Xilinx Spartan-IIE PQ208 Rev1.01 (HDR2.18), SL_FPGA_Auto_2E (U1.166)
HARD_TCK: SL1 Xilinx Spartan-IIE PQ208 Rev1.01 (HDR1.3), SL_Config_2E (U5.6), SL_FPGA_Auto_2E (U1.207)
HARD_TDI: SL1 Xilinx Spartan-IIE PQ208 Rev1.01 (HDR1.1), SL_FPGA_Auto_2E (U1.159)
HARD_TDO: SL1 Xilinx Spartan-IIE PQ208 Rev1.01 (HDR1.2), SL_Config_2E (U5.17)
HARD_TMS: SL1 Xilinx Spartan-IIE PQ208 Rev1.01 (HDR1.4), SL_Config_2E (U5.5), SL_FPGA_Auto_2E (U1.2)
HB2: SL1 Xilinx Spartan-IIE PQ208 Rev1.01 (HDR3.2), SL_FPGA_Auto_2E (U1.163)
HB3: SL1 Xilinx Spartan-IIE PQ208 Rev1.01 (HDR3.3), SL_FPGA_Auto_2E (U1.160)
HB4: SL1 Xilinx Spartan-IIE PQ208 Rev1.01 (HDR3.4), SL_FPGA_Auto_2E (U1.162)
HB5: SL1 Xilinx Spartan-IIE PQ208 Rev1.01 (HDR3.5), SL_FPGA_Auto_2E (U1.138)
HB6: SL1 Xilinx Spartan-IIE PQ208 Rev1.01 (HDR3.6), SL_FPGA_Auto_2E (U1.161)
HB7: SL1 Xilinx Spartan-IIE PQ208 Rev1.01 (HDR3.7), SL_FPGA_Auto_2E (U1.135)
HB8: SL1 Xilinx Spartan-IIE PQ208 Rev1.01 (HDR3.8), SL_FPGA_Auto_2E (U1.136)
HB9: SL1 Xilinx Spartan-IIE PQ208 Rev1.01 (HDR3.9), SL_FPGA_Auto_2E (U1.133)
HB10: SL1 Xilinx Spartan-IIE PQ208 Rev1.01 (HDR3.10), SL_FPGA_Auto_2E (U1.134)
HB11: SL1 Xilinx Spartan-IIE PQ208 Rev1.01 (HDR3.11), SL_FPGA_Auto_2E (U1.129)
HB12: SL1 Xilinx Spartan-IIE PQ208 Rev1.01 (HDR3.12), SL_FPGA_Auto_2E (U1.132)
HB13: SL1 Xilinx Spartan-IIE PQ208 Rev1.01 (HDR3.13), SL_FPGA_Auto_2E (U1.126)
HB14: SL1 Xilinx Spartan-IIE PQ208 Rev1.01 (HDR3.14), SL_FPGA_Auto_2E (U1.127)
HB15: SL1 Xilinx Spartan-IIE PQ208 Rev1.01 (HDR3.15), SL_FPGA_Auto_2E (U1.123)
HB16: SL1 Xilinx Spartan-IIE PQ208 Rev1.01 (HDR3.16), SL_FPGA_Auto_2E (U1.125)
HB17: SL1 Xilinx Spartan-IIE PQ208 Rev1.01 (HDR3.17), SL_FPGA_Auto_2E (U1.121)
HB18: SL1 Xilinx Spartan-IIE PQ208 Rev1.01 (HDR3.18), SL_FPGA_Auto_2E (U1.122)
HB19: SL1 Xilinx Spartan-IIE PQ208 Rev1.01 (HDR3.19), SL_FPGA_Auto_2E (U1.120)
~{INIT}: SL_Config_2E (R5.2 U5.8), SL_FPGA_Auto_2E (U1.107)
JTAG_NEXUS_TCK: SL1 Xilinx Spartan-IIE PQ208 Rev1.01 (HDR1.7), SL_FPGA_Auto_2E (U1.6)
JTAG_NEXUS_TDI: SL1 Xilinx Spartan-IIE PQ208 Rev1.01 (HDR1.5), SL_FPGA_Auto_2E (U1.4)
JTAG_NEXUS_TDO: SL1 Xilinx Spartan-IIE PQ208 Rev1.01 (HDR1.6), SL_FPGA_Auto_2E (U1.5)
JTAG_NEXUS_TMS: SL1 Xilinx Spartan-IIE PQ208 Rev1.01 (HDR1.8), SL_FPGA_Auto_2E (U1.7)
LCD_DB0: SL_LCD_SW_LED_2E (RA2.5), SL_FPGA_Auto_2E (U1.20)
LCD_DB1: SL_LCD_SW_LED_2E (RA2.6), SL_FPGA_Auto_2E (U1.18)
LCD_DB2: SL_LCD_SW_LED_2E (RA2.7), SL_FPGA_Auto_2E (U1.17)
LCD_DB3: SL_LCD_SW_LED_2E (RA2.8), SL_FPGA_Auto_2E (U1.16)
LCD_DB4: SL_LCD_SW_LED_2E (RA3.5), SL_FPGA_Auto_2E (U1.15)
LCD_DB5: SL_LCD_SW_LED_2E (RA3.6), SL_FPGA_Auto_2E (U1.11)
LCD_DB6: SL_LCD_SW_LED_2E (RA3.7), SL_FPGA_Auto_2E (U1.10)
LCD_DB7: SL_LCD_SW_LED_2E (RA3.8), SL_FPGA_Auto_2E (U1.9)
LCD_E: SL_LCD_SW_LED_2E (RA1.8), SL_FPGA_Auto_2E (U1.21)
LCD_LIGHT: SL_LCD_SW_LED_2E (R2.1), SL_FPGA_Auto_2E (U1.8)
LCD_RS: SL_LCD_SW_LED_2E (RA1.6), SL_FPGA_Auto_2E (U1.23)
LCD_RW: SL_LCD_SW_LED_2E (RA1.7), SL_FPGA_Auto_2E (U1.22)
LEDS0: SL_LCD_SW_LED_2E (LED0.1), SL_FPGA_Auto_2E (U1.102)
LEDS1: SL_LCD_SW_LED_2E (LED1.1), SL_FPGA_Auto_2E (U1.101)
LEDS2: SL_LCD_SW_LED_2E (LED2.1), SL_FPGA_Auto_2E (U1.100)
LEDS3: SL_LCD_SW_LED_2E (LED3.1), SL_FPGA_Auto_2E (U1.99)
LEDS4: SL_LCD_SW_LED_2E (LED4.1), SL_FPGA_Auto_2E (U1.98)
LEDS5: SL_LCD_SW_LED_2E (LED5.1), SL_FPGA_Auto_2E (U1.97)
LEDS6: SL_LCD_SW_LED_2E (LED6.1), SL_FPGA_Auto_2E (U1.96)
LEDS7: SL_LCD_SW_LED_2E (LED7.1), SL_FPGA_Auto_2E (U1.95)
M0: SL1 Xilinx Spartan-IIE PQ208 Rev1.01 (JP5.1 R7.2), SL_FPGA_Auto_2E (U1.52)
PROG_B: SL_Config_2E (R6.2 U5.7), SL_FPGA_Auto_2E (U1.106)
SW0: SL_LCD_SW_LED_2E (RA7.1 S2.16), SL_FPGA_Auto_2E (U1.108)
SW1: SL_LCD_SW_LED_2E (RA7.2 S2.15), SL_FPGA_Auto_2E (U1.109)
SW2: SL_LCD_SW_LED_2E (RA7.3 S2.14), SL_FPGA_Auto_2E (U1.110)
SW3: SL_LCD_SW_LED_2E (RA7.4 S2.13), SL_FPGA_Auto_2E (U1.111)
SW4: SL_LCD_SW_LED_2E (RA8.1 S2.12), SL_FPGA_Auto_2E (U1.112)
SW5: SL_LCD_SW_LED_2E (RA8.2 S2.11), SL_FPGA_Auto_2E (U1.113)
SW6: SL_LCD_SW_LED_2E (RA8.3 S2.10), SL_FPGA_Auto_2E (U1.114)
SW7: SL_LCD_SW_LED_2E (RA8.4 S2.9), SL_FPGA_Auto_2E (U1.115)
TDI_C: SL_Config_2E (U5.4), SL_FPGA_Auto_2E (U1.157)
TEST: SL_LCD_SW_LED_2E (R16.2 S3.1 S3.2), SL_FPGA_Auto_2E (U1.27)
Xout_Alt: SL1 Xilinx Spartan-IIE PQ208 Rev1.01 (JP3.1 R22.1), SL_FPGA_Auto_2E (U1.30)
Yout_Alt: SL1 Xilinx Spartan-IIE PQ208 Rev1.01 (JP4.1 R21.1), SL_FPGA_Auto_2E (U1.31)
